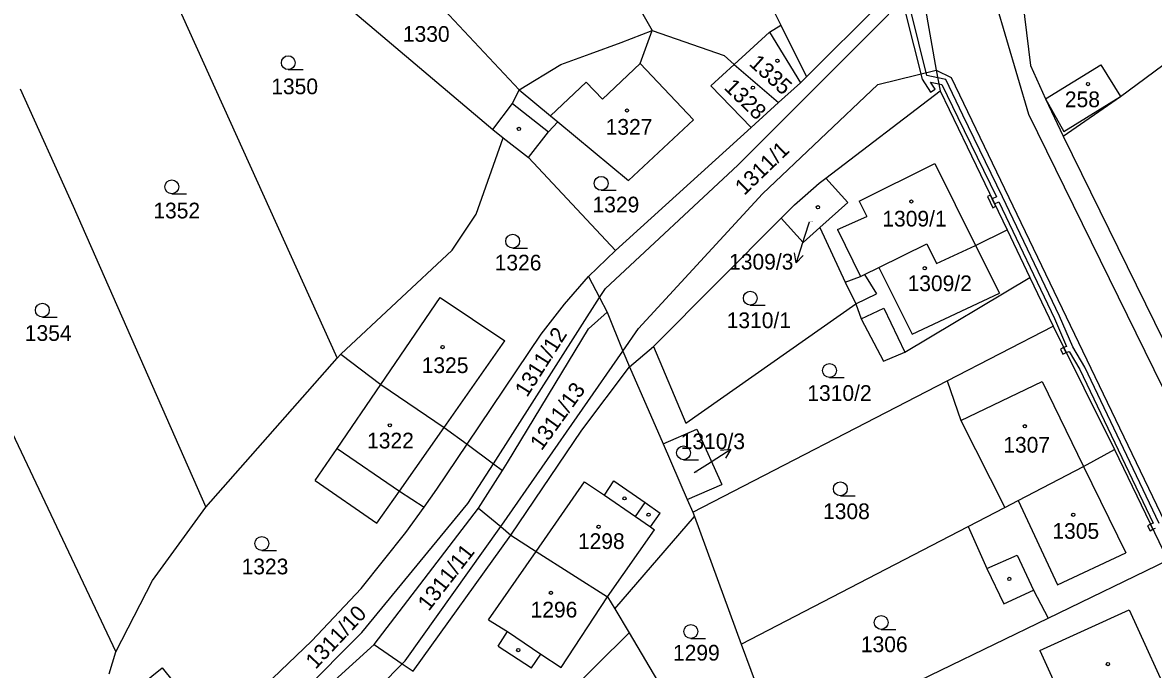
# Model space of a CAD drawing. Extents: x -785744 to -782822, y -1067550 to -1063910.
# Drawn here: x -783972 to -783849.7, y -1065472 to -1065402 of the extents above; entities that cross this region are included whole.
import ezdxf

# ---------------------------------------------------------------- set-up
doc = ezdxf.new("R2010")
doc.units = 0
for name, color, linetype in [('Hranice parcel', 7, 'Continuous'), ('Parcelní čísla', 7, 'Continuous'), ('Pop_ČP_popisy', 7, 'Continuous'), ('Vnitřní kresba', 7, 'Continuous'), ('Věcná břemena k části', 7, 'Continuous'), ('Značky budov', 7, 'Continuous'), ('Značky kultur', 7, 'Continuous')]:
    doc.layers.add(name, color=color, linetype=linetype)

msp = doc.modelspace()

# ---------------------------------------------------------------- linework, layer by layer
at = {"layer": 'Hranice parcel'}
for p, q in [((-783885.15, -1065418.83), (-783872.79, -1065409.37)), ((-783885.85, -1065419.37), (-783885.15, -1065418.83)), ((-783882.77, -1065421.45), (-783885.15, -1065418.83)), ((-783889.96, -1065423.16), (-783888.52, -1065421.71)), ((-783885.78, -1065424.16), (-783882.77, -1065421.45)), ((-783903.79, -1065437.02), (-783889.96, -1065423.16)), ((-783889.96, -1065423.16), (-783887.59, -1065425.78)), ((-783887.59, -1065425.78), (-783885.78, -1065424.16)), ((-783885.78, -1065424.16), (-783883.05, -1065430.06))]:
    msp.add_line(p, q, dxfattribs=at)
for points in [[(-783959.8, -1065390.03), (-783937.99, -1065438.3)], [(-783895.08, -1065392.06), (-783890, -1065402.26)], [(-783864.73, -1065392.45), (-783863.01, -1065406.62)], [(-783932.89, -1065393.65), (-783918.29, -1065409.27)], [(-783875.16, -1065396.04), (-783873.19, -1065407.14)], [(-783940.02, -1065397.56), (-783921.15, -1065413.57)], [(-783906.35, -1065398.6), (-783903.91, -1065402.85)], [(-783853.28, -1065410), (-783837.73, -1065398.45)], [(-783887.22, -1065407.86), (-783879.28, -1065399.94)], [(-783907.28, -1065404.14), (-783903.91, -1065402.85)], [(-783905.21, -1065406.41), (-783903.91, -1065402.85)], [(-783903.91, -1065402.85), (-783896.12, -1065405.54)], [(-783895.05, -1065406.52), (-783891.24, -1065403.04)], [(-783891.24, -1065403.04), (-783890, -1065402.26)], [(-783890, -1065402.26), (-783887.22, -1065407.86)], [(-783910.64, -1065405.36), (-783907.28, -1065404.14)], [(-783913.8, -1065406.53), (-783910.64, -1065405.36)], [(-783918.29, -1065409.27), (-783913.8, -1065406.53)], [(-783905.21, -1065406.41), (-783899.45, -1065412.5)], [(-783897.58, -1065408.82), (-783895.05, -1065406.52)], [(-783896.12, -1065405.54), (-783895.05, -1065406.52)], [(-783895.05, -1065406.52), (-783890.27, -1065410.65)], [(-783863.01, -1065406.62), (-783861.4, -1065410.24)], [(-783861.4, -1065410.24), (-783855.39, -1065406.55)], [(-783855.39, -1065406.55), (-783853.28, -1065410)], [(-783887.89, -1065408.5), (-783887.22, -1065407.86)], [(-783873.19, -1065407.14), (-783872.79, -1065409.37)], [(-783972.25, -1065409.17), (-783966.54, -1065421.85)], [(-783897.58, -1065408.82), (-783893.23, -1065413.32)], [(-783890.27, -1065410.65), (-783887.89, -1065408.5)], [(-783919.01, -1065410.74), (-783918.29, -1065409.27)], [(-783872.79, -1065409.37), (-783869.86, -1065415.43)], [(-783861.4, -1065410.24), (-783859.49, -1065414.26)], [(-783859.49, -1065414.26), (-783853.28, -1065410)], [(-783921.15, -1065413.57), (-783919.01, -1065410.74)], [(-783893.23, -1065413.32), (-783890.27, -1065410.65)], [(-783915.12, -1065413.82), (-783914.12, -1065412.71)], [(-783914.12, -1065412.71), (-783906.48, -1065419.07)], [(-783906.48, -1065419.07), (-783899.45, -1065412.5)], [(-783921.15, -1065413.57), (-783920.02, -1065414.46)], [(-783917.31, -1065416.6), (-783915.12, -1065413.82)], [(-783907.87, -1065426.66), (-783893.23, -1065413.32)], [(-783922.96, -1065422.71), (-783920.02, -1065414.46)], [(-783920.02, -1065414.46), (-783917.31, -1065416.6)], [(-783859.49, -1065414.26), (-783844.65, -1065444.45)], [(-783869.86, -1065415.43), (-783865.53, -1065424.41)], [(-783917.31, -1065416.6), (-783907.87, -1065426.66)], [(-783887.38, -1065420.71), (-783885.85, -1065419.37)], [(-783985.3, -1065420.68), (-783961.91, -1065470.05)], [(-783888.52, -1065421.71), (-783887.38, -1065420.71)], [(-783966.54, -1065421.85), (-783952.2, -1065454.41)], [(-783925.56, -1065426.6), (-783922.96, -1065422.71)], [(-783868.94, -1065426.09), (-783865.53, -1065424.41)], [(-783865.53, -1065424.41), (-783863.07, -1065429.56)], [(-783879.39, -1065428.47), (-783874.23, -1065425.91)], [(-783874.23, -1065425.91), (-783873.17, -1065428.05)], [(-783873.17, -1065428.05), (-783868.94, -1065426.09)], [(-783937.59, -1065437.87), (-783925.56, -1065426.6)], [(-783910.82, -1065429.47), (-783907.87, -1065426.66)], [(-783880.95, -1065429.24), (-783879.39, -1065428.47)], [(-783913.39, -1065432.44), (-783910.82, -1065429.47)], [(-783910.82, -1065429.47), (-783909.62, -1065431.74)], [(-783880.95, -1065429.24), (-783879.66, -1065431.32)], [(-783876.59, -1065437.63), (-783863.07, -1065429.56)], [(-783863.07, -1065429.56), (-783860.57, -1065434.84)], [(-783883.05, -1065430.06), (-783881.89, -1065432.42)], [(-783933.26, -1065441.13), (-783926.83, -1065431.72)], [(-783926.83, -1065431.72), (-783919.85, -1065436.43)], [(-783909.62, -1065431.74), (-783908.77, -1065433.33)], [(-783900.27, -1065445.31), (-783881.89, -1065432.42)], [(-783881.89, -1065432.42), (-783879.66, -1065431.32)], [(-783881.89, -1065432.42), (-783881.31, -1065434.05)], [(-783915.92, -1065435.68), (-783913.39, -1065432.44)], [(-783910.8, -1065435.12), (-783908.77, -1065433.33)], [(-783908.77, -1065433.33), (-783907.1, -1065437.53)], [(-783881.31, -1065434.05), (-783878.89, -1065438.6)], [(-783872.02, -1065440.75), (-783860.57, -1065434.84)], [(-783860.57, -1065434.84), (-783853.92, -1065448.16)], [(-783923.94, -1065447.6), (-783915.92, -1065435.68)], [(-783919.56, -1065449.56), (-783910.8, -1065435.12)], [(-783926.4, -1065445.78), (-783919.85, -1065436.43)], [(-783906.38, -1065439.22), (-783903.79, -1065437.02)], [(-783903.79, -1065437.02), (-783900.27, -1065445.31)], [(-783952.2, -1065454.41), (-783937.99, -1065438.3)], [(-783937.99, -1065438.3), (-783937.59, -1065437.87)], [(-783937.59, -1065437.87), (-783933.26, -1065441.13)], [(-783907.1, -1065437.53), (-783906.38, -1065439.22)], [(-783878.89, -1065438.6), (-783876.59, -1065437.63)], [(-783911.52, -1065446.07), (-783906.38, -1065439.22)], [(-783906.38, -1065439.22), (-783902.74, -1065447.57)], [(-783899.53, -1065454.96), (-783872.02, -1065440.75)], [(-783872.02, -1065440.75), (-783870.55, -1065445.04)], [(-783938, -1065448.06), (-783933.26, -1065441.13)], [(-783933.26, -1065441.13), (-783926.4, -1065445.78)], [(-783926.4, -1065445.78), (-783923.94, -1065447.6)], [(-783870.55, -1065445.04), (-783865.79, -1065454.44)], [(-783919.2, -1065457.42), (-783911.52, -1065446.07)], [(-783902.74, -1065447.57), (-783899.09, -1065445.98)], [(-783899.09, -1065445.98), (-783896.39, -1065451.94)], [(-783940.37, -1065451.53), (-783938, -1065448.06)], [(-783927.22, -1065452.44), (-783923.94, -1065447.6)], [(-783923.94, -1065447.6), (-783921.09, -1065449.7)], [(-783902.74, -1065447.57), (-783900.13, -1065453.57)], [(-783857.27, -1065449.99), (-783853.92, -1065448.16)], [(-783853.92, -1065448.16), (-783848.15, -1065460.14)], [(-783922.69, -1065454.5), (-783920.11, -1065450.43)], [(-783921.09, -1065449.7), (-783920.11, -1065450.43)], [(-783920.11, -1065450.43), (-783919.56, -1065449.56)], [(-783864.34, -1065453.68), (-783857.27, -1065449.99)], [(-783940.37, -1065451.53), (-783933.68, -1065456.14)], [(-783900.13, -1065453.57), (-783896.39, -1065451.94)], [(-783933.68, -1065456.14), (-783931.24, -1065452.67)], [(-783931.24, -1065452.67), (-783928.59, -1065454.39)], [(-783928.59, -1065454.39), (-783927.22, -1065452.44)], [(-783957.97, -1065462.32), (-783952.2, -1065454.41)], [(-783930.55, -1065457.16), (-783928.59, -1065454.39)], [(-783900.13, -1065453.57), (-783899.53, -1065454.96)], [(-783865.79, -1065454.44), (-783864.34, -1065453.68)], [(-783933.97, -1065469.26), (-783922.69, -1065454.5)], [(-783922.69, -1065454.5), (-783920.29, -1065456.51)], [(-783907.97, -1065465.4), (-783899.35, -1065455.42)], [(-783899.53, -1065454.96), (-783899.35, -1065455.42)], [(-783899.35, -1065455.42), (-783894.31, -1065469.23)], [(-783869.75, -1065456.49), (-783865.79, -1065454.44)], [(-783920.29, -1065456.51), (-783919.2, -1065457.42)], [(-783894.31, -1065469.23), (-783869.75, -1065456.49)], [(-783869.75, -1065456.49), (-783867.72, -1065461.03)], [(-783935.38, -1065463.19), (-783930.55, -1065457.16)], [(-783929.77, -1065472.16), (-783919.2, -1065457.42)], [(-783919.2, -1065457.42), (-783916.45, -1065459.19)], [(-783916.45, -1065459.19), (-783908.74, -1065464.1)], [(-783861.08, -1065466.4), (-783848.15, -1065460.14)], [(-783867.72, -1065461.03), (-783865.88, -1065464.87)], [(-783961.91, -1065470.05), (-783957.97, -1065462.32)], [(-783940.73, -1065468.87), (-783935.38, -1065463.19)], [(-783908.74, -1065464.1), (-783907.97, -1065465.4)], [(-783865.88, -1065464.87), (-783862.69, -1065463.4)], [(-783862.69, -1065463.4), (-783861.08, -1065466.4)], [(-783907.97, -1065465.4), (-783906.42, -1065468.01)], [(-783890.12, -1065480.46), (-783861.08, -1065466.4)], [(-783862, -1065469.91), (-783852.35, -1065465.5)], [(-783852.35, -1065465.5), (-783847.46, -1065476.19)], [(-783949.2, -1065476.97), (-783940.73, -1065468.87)], [(-783916.95, -1065478.46), (-783906.42, -1065468.01)], [(-783906.42, -1065468.01), (-783896.28, -1065485.16)], [(-783962.65, -1065472.45), (-783961.91, -1065470.05)], [(-783948.02, -1065481.98), (-783933.97, -1065469.26)], [(-783933.97, -1065469.26), (-783930.94, -1065471.35)], [(-783894.31, -1065469.23), (-783890.12, -1065480.46)], [(-783862, -1065469.91), (-783857.13, -1065480.61)], [(-783930.94, -1065471.35), (-783929.77, -1065472.16)], [(-783960.08, -1065474.35), (-783956.91, -1065471.8)], [(-783956.91, -1065471.8), (-783953.19, -1065476.4)]]:
    msp.add_lwpolyline(points, dxfattribs=at)
at = {"layer": 'Pop_ČP_popisy'}
for p, q in [((-783887.45, -1065425.13), (-783888.36, -1065427.99)), ((-783897.95, -1065449.75), (-783895.43, -1065448.13))]:
    msp.add_line(p, q, dxfattribs=at)
for points in [[(-783886.95, -1065423.57), (-783887.45, -1065425.13)], [(-783887.58, -1065427.19), (-783888.36, -1065427.99), (-783888.53, -1065426.88)], [(-783896.54, -1065448.25), (-783895.43, -1065448.13), (-783896, -1065449.09)], [(-783899.36, -1065450.66), (-783897.95, -1065449.75)]]:
    msp.add_lwpolyline(points, dxfattribs=at)
at = {"layer": 'Vnitřní kresba'}
for points in [[(-783866.79, -1065399.79), (-783863.21, -1065411.89)], [(-783894.64, -1065417.41), (-783878.34, -1065401.09)], [(-783891.24, -1065403.04), (-783887.89, -1065408.5)], [(-783909.29, -1065410.28), (-783905.21, -1065406.41)], [(-783879.51, -1065408.68), (-783873.19, -1065407.14)], [(-783873.19, -1065407.14), (-783871.6, -1065407.94)], [(-783871.6, -1065407.94), (-783827.62, -1065499.48)], [(-783914.9, -1065412.07), (-783911.05, -1065408.42)], [(-783911.05, -1065408.42), (-783909.29, -1065410.28)], [(-783892, -1065420.52), (-783879.51, -1065408.68)], [(-783918.29, -1065409.27), (-783914.9, -1065412.07)], [(-783861.4, -1065410.24), (-783859.41, -1065413.77)], [(-783859.41, -1065413.77), (-783853.28, -1065410)], [(-783919.01, -1065410.74), (-783915.12, -1065413.82)], [(-783914.9, -1065412.07), (-783914.12, -1065412.71)], [(-783863.21, -1065411.89), (-783848.68, -1065441.49)], [(-783908.98, -1065430.74), (-783894.64, -1065417.41)], [(-783881.54, -1065421.29), (-783873.36, -1065417.22)], [(-783873.36, -1065417.22), (-783868.94, -1065426.09)], [(-783905.39, -1065435.07), (-783892, -1065420.52)], [(-783881.54, -1065421.29), (-783880.69, -1065422.98)], [(-783883.86, -1065424.36), (-783880.69, -1065422.98)], [(-783883.86, -1065424.36), (-783881.4, -1065429.46)], [(-783868.94, -1065426.09), (-783866.36, -1065431.26)], [(-783879.39, -1065428.47), (-783875.81, -1065435.68)], [(-783883.05, -1065430.06), (-783881.4, -1065429.46)], [(-783881.4, -1065429.46), (-783880.95, -1065429.24)], [(-783909.62, -1065431.74), (-783908.98, -1065430.74)], [(-783921.09, -1065449.7), (-783909.62, -1065431.74)], [(-783875.81, -1065435.68), (-783866.36, -1065431.26)], [(-783881.31, -1065434.05), (-783878.88, -1065432.87)], [(-783878.88, -1065432.87), (-783876.59, -1065437.63)], [(-783907.1, -1065437.53), (-783905.39, -1065435.07)], [(-783920.18, -1065456.36), (-783907.1, -1065437.53)], [(-783870.55, -1065445.04), (-783861.74, -1065440.82)], [(-783861.74, -1065440.82), (-783857.27, -1065449.99)], [(-783931.24, -1065452.67), (-783926.4, -1065445.78)], [(-783938, -1065448.06), (-783931.24, -1065452.67)], [(-783923.84, -1065454), (-783921.09, -1065449.7)], [(-783857.27, -1065449.99), (-783852.71, -1065459.36)], [(-783916.45, -1065459.19), (-783911.22, -1065451.67)], [(-783911.22, -1065451.67), (-783909.07, -1065453.09)], [(-783909.07, -1065453.09), (-783908.05, -1065451.55)], [(-783908.05, -1065451.55), (-783904.67, -1065453.91)], [(-783909.07, -1065453.09), (-783905.72, -1065455.41)], [(-783935.31, -1065467.96), (-783923.84, -1065454)], [(-783905.72, -1065455.41), (-783904.67, -1065453.91)], [(-783904.67, -1065453.91), (-783903.05, -1065455.06)], [(-783864.34, -1065453.68), (-783860.07, -1065462.8)], [(-783905.72, -1065455.41), (-783904.1, -1065456.55)], [(-783904.1, -1065456.55), (-783903.05, -1065455.06)], [(-783930.62, -1065471.03), (-783920.29, -1065456.51)], [(-783920.29, -1065456.51), (-783920.18, -1065456.36)], [(-783908.74, -1065464.1), (-783903.65, -1065456.86)], [(-783904.1, -1065456.55), (-783903.65, -1065456.86)], [(-783921.6, -1065466.6), (-783916.45, -1065459.19)], [(-783867.72, -1065461.03), (-783864.44, -1065459.59)], [(-783864.44, -1065459.59), (-783862.69, -1065463.4)], [(-783860.07, -1065462.8), (-783852.71, -1065459.36)], [(-783913.76, -1065471.75), (-783908.74, -1065464.1)], [(-783921.6, -1065466.6), (-783919.58, -1065467.86)], [(-783920.58, -1065469.44), (-783919.58, -1065467.86)], [(-783919.58, -1065467.86), (-783915.97, -1065470.29)], [(-783948.41, -1065481.11), (-783935.31, -1065467.96)], [(-783920.58, -1065469.44), (-783916.97, -1065471.8)], [(-783916.97, -1065471.8), (-783915.97, -1065470.29)], [(-783915.97, -1065470.29), (-783913.76, -1065471.75)], [(-783944.84, -1065485.46), (-783930.94, -1065471.35)], [(-783930.94, -1065471.35), (-783930.62, -1065471.03)]]:
    msp.add_lwpolyline(points, dxfattribs=at)
at = {"layer": 'Věcná břemena k části'}
for points in [[(-783876.52, -1065400.97), (-783874.73, -1065408.1)], [(-783874.2, -1065407.73), (-783875.96, -1065400.71)], [(-783872.17, -1065408.16), (-783873.04, -1065407.97), (-783874.2, -1065407.73)], [(-783874.73, -1065408.1), (-783873.83, -1065409.5), (-783873.33, -1065409.18), (-783873.81, -1065408.42), (-783872.93, -1065408.61), (-783872.59, -1065408.68)], [(-783872.59, -1065408.68), (-783870.87, -1065412.27)], [(-783870.33, -1065412.01), (-783872.17, -1065408.16)], [(-783870.87, -1065412.27), (-783866.69, -1065420.84)], [(-783866.02, -1065420.85), (-783870.33, -1065412.01)], [(-783867.34, -1065420.66), (-783867.65, -1065420.81)], [(-783867.65, -1065420.81), (-783867.09, -1065422.01)], [(-783866.76, -1065421.86), (-783866.89, -1065421.59), (-783867.15, -1065421.05), (-783867.34, -1065420.66)], [(-783866.69, -1065420.84), (-783867.15, -1065421.05)], [(-783867.15, -1065421.05), (-783866.89, -1065421.59), (-783866.43, -1065421.38)], [(-783866.43, -1065421.38), (-783860.41, -1065433.98)], [(-783859.87, -1065433.74), (-783866.02, -1065420.85)], [(-783867.09, -1065422.01), (-783866.76, -1065421.86)], [(-783860.41, -1065433.98), (-783859.11, -1065437.03)], [(-783858.44, -1065437.05), (-783859.87, -1065433.74)], [(-783859.42, -1065437.14), (-783859.78, -1065437.32)], [(-783859.11, -1065437.03), (-783859.42, -1065437.14)], [(-783859.15, -1065437.68), (-783859.42, -1065437.14)], [(-783859.42, -1065437.14), (-783859.15, -1065437.68), (-783858.84, -1065437.57)], [(-783857.14, -1065439.25), (-783858.44, -1065437.05)], [(-783859.78, -1065437.32), (-783859.52, -1065437.86)], [(-783859.52, -1065437.86), (-783859.15, -1065437.68)], [(-783858.84, -1065437.57), (-783857.68, -1065439.53)], [(-783857.68, -1065439.53), (-783849.75, -1065456.15)], [(-783849.08, -1065456.17), (-783857.14, -1065439.25)], [(-783850.02, -1065456.26), (-783850.34, -1065456.41)], [(-783850.34, -1065456.41), (-783850.06, -1065456.96)], [(-783850.06, -1065456.96), (-783849.76, -1065456.8)], [(-783849.75, -1065456.15), (-783850.02, -1065456.26)], [(-783849.76, -1065456.8), (-783850.02, -1065456.26)], [(-783850.02, -1065456.26), (-783849.76, -1065456.8)], [(-783849.76, -1065456.8), (-783849.49, -1065456.69)]]:
    msp.add_lwpolyline(points, dxfattribs=at)
at = {"layer": 'Značky budov'}
for centre in [(-783890.37, -1065406.12), (-783893.03, -1065409.03), (-783856.79, -1065408.64), (-783906.64, -1065411.5), (-783918.33, -1065413.49), (-783875.89, -1065421.34), (-783886, -1065421.96), (-783874.44, -1065428.56), (-783926.58, -1065437.09), (-783932.29, -1065445.55), (-783863.62, -1065445.65), (-783906.91, -1065453.45), (-783904.31, -1065455.22), (-783858.38, -1065455.23), (-783909.71, -1065456.52), (-783865.3, -1065462.16), (-783914.87, -1065463.67), (-783918.4, -1065469.87), (-783854.64, -1065471.38)]:
    msp.add_circle(centre, 0.175, dxfattribs=at)
at = {"layer": 'Značky kultur'}
for p, q in [((-783943.27, -1065407.08), (-783941.67, -1065407.08)), ((-783909.43, -1065420.13), (-783907.83, -1065420.13)), ((-783955.87, -1065420.51), (-783954.27, -1065420.51)), ((-783919, -1065426.38), (-783917.4, -1065426.38)), ((-783893.31, -1065432.55), (-783891.71, -1065432.55)), ((-783969.86, -1065433.85), (-783968.26, -1065433.85)), ((-783884.74, -1065440.37), (-783883.14, -1065440.37)), ((-783900.52, -1065449.27), (-783898.92, -1065449.27)), ((-783883.57, -1065453.17), (-783881.97, -1065453.17)), ((-783946.13, -1065459.09), (-783944.53, -1065459.09)), ((-783879.16, -1065467.62), (-783877.56, -1065467.62)), ((-783899.74, -1065468.6), (-783898.14, -1065468.6))]:
    msp.add_line(p, q, dxfattribs=at)
for centre in [(-783943.27, -1065406.33), (-783909.43, -1065419.38), (-783955.87, -1065419.76), (-783919, -1065425.63), (-783893.31, -1065431.8), (-783969.86, -1065433.1), (-783884.74, -1065439.62), (-783900.52, -1065448.52), (-783883.57, -1065452.42), (-783946.13, -1065458.34), (-783879.16, -1065466.87), (-783899.74, -1065467.85)]:
    msp.add_circle(centre, 0.75, dxfattribs=at)

# ---------------------------------------------------------------- texts
at = {"layer": 'Parcelní čísla'}
for s, height, p in [('1330', 1.7, (-783930.88, -1065404.07)), ('1350', 1.7, (-783945.11, -1065409.74)), ('258', 1.7, (-783859.29, -1065411.14)), ('1327', 1.7, (-783908.95, -1065414.12)), ('1329', 1.7, (-783910.37, -1065422.52)), ('1352', 1.7, (-783957.86, -1065423.17)), ('1309/1', 1.7, (-783879.03, -1065424.05)), ('1309/3', 0.1, (-783886.95, -1065423.57)), ('1326', 1.7, (-783920.95, -1065428.8)), ('1309/2', 1.7, (-783876.3, -1065431.04)), ('1310/1', 1.7, (-783895.86, -1065435.04)), ('1354', 1.7, (-783971.76, -1065436.42)), ('1325', 1.7, (-783928.84, -1065439.9)), ('1310/2', 1.7, (-783887.14, -1065442.91)), ('1322', 1.7, (-783934.75, -1065448.05)), ('1307', 1.7, (-783865.95, -1065448.51)), ('1310/3', 0.1, (-783899.36, -1065450.66)), ('1308', 1.7, (-783885.44, -1065455.7)), ('1305', 1.7, (-783860.64, -1065457.83)), ('1298', 1.7, (-783911.95, -1065458.93)), ('1323', 1.7, (-783948.32, -1065461.67)), ('1296', 1.7, (-783917.07, -1065466.34)), ('1306', 1.7, (-783881.35, -1065470.09)), ('1299', 1.7, (-783901.67, -1065471))]:
    msp.add_text(s, height=height, dxfattribs=at).set_placement(p)
for s, rotation, p in [('1335', 318.1341, (-783893.53, -1065406.55)), ('1328', 315.9022, (-783896.24, -1065409.11)), ('1311/1', 44.0425, (-783893.96, -1065420.75)), ('1311/12', 57.6147, (-783917.45, -1065442.6)), ('1311/13', 54.1624, (-783915.88, -1065448.37)), ('1311/11', 52.1165, (-783928.07, -1065465.73)), ('1311/10', 46.806, (-783940.32, -1065472.02))]:
    msp.add_text(s, height=1.7, rotation=rotation, dxfattribs=at).set_placement(p)
at = {"layer": 'Pop_ČP_popisy'}
for s, p in [('1309/3', (-783895.6, -1065428.71)), ('1310/3', (-783900.83, -1065448.13))]:
    msp.add_text(s, height=1.7, dxfattribs=at).set_placement(p)

doc.saveas('drawing.dxf')
